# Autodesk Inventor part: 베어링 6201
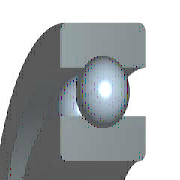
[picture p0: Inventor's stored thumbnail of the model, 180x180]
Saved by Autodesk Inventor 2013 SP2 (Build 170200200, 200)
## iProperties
Created: 2015-12
Part Number: 베어링 6201
Material: 강철, 연강
Description: 깊은 그루브 볼 베어링
Document SubType Name: Modeling
Standard: KS B 2023
Designer: mdu
Standards Organization: KS
Language: ko-KR
Size Designation: 6201 - 12 x 32 x 10
Categories: <MemberInstance><Categories><Category DisplayName="샤프트 부품" InternalName="7f7aeb1f-a693-4053-b835-cee3144e0d98" Mnemonic="SHFT"><Category DisplayName="베어링" Inter
Density: 7.86 g/cm^3
Mass: 36.8026 g
Surface Area: 42.5728 cm^2
Volume: 4.68226 cm^3
Company: 한국ATC센터
IsCustomPart: 1
Author: mdu
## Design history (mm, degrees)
sketch "스케치" dims "d0" = 5.2 (= -0.26 x WD + 0.26 x BD)
  geometry: L1 (2.4, 11)-(7.6, 11); L2 (5, 11)-(5, 8.4); L3 (5, 11)-(5, 13.6); L4 (3.068, 9.26)-(0, 9.26); L5 (0, 6)-(10, 6); L6 (3.068, 12.74)-(0, 12.74); L7 (0, 16)-(10, 16); L8 (10, 6)-(10, 9.26); L9 (6.932, 9.26)-(10, 9.26); L10 (6.932, 12.74)-(10, 12.74); L11 (10, 16)-(10, 12.74); L12 (-1.4, 0)-(8.4, 0) reference; L13 (0, -0.3)-(0, 5.3) reference
  constraints: 22 end point, 4 point on line, 2 collinear, 2 perpendicular, 2 symmetric about line, 1 midpoint, 1 parallel, 14 other
  dimensions: "d9" = 12 diameter of L5 L12 (= WD); "d11" = 32 diameter of L7 L12 (= BD); "d12" = 10 distance between parallel lines of L8 L13 (= KB); "d13" = 18.52 diameter of L9 L12 (= 0.326 x BD + 0.674 x WD)
revolve "본체" stored, may be unused: angle "d6" = 90 deg
revolve "볼" stored, may be unused: angle "d7" = 90 deg
pattern_circular "IDS_ARRAYBALL[SIMPL:T]" dims angle "d3" = 360 deg
body "Solid1"
fillet "모깎기1" dims "d1" = 0.6 (= KRS)
other parameters: "WD" = 12 [user parameter; used in 5 equation terms], "BD" = 32 [user parameter; used in 5 equation terms], "KB" = 10 [user parameter; used in 1 equation term], "KRS" = 0.6 [user parameter; used in 1 equation term], "d4" = 0, "d5" = 0, "d8" = 0, "d14" = 0, "d15" = 0, "BBA" = 0 [user parameter], "BC0" = 3100000 [user parameter], "BC" = 6890000 [user parameter], "BR" = 16 (= 0.5 x BD) [user parameter], "WR" = 6 (= 0.5 x WD) [user parameter]
